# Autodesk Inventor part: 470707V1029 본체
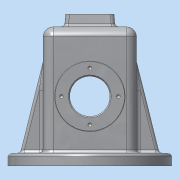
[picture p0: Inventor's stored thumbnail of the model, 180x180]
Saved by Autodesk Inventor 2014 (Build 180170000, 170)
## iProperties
Created: 2017-07
Part Number: 470707V1029 본체
Material: 알루미늄 6061
Document SubType Name: Modeling
Designer: 406-9
Density: 2.71 g/cm^3
Appearance: 알루미늄 - 평지
Author: 406-9
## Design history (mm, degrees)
sketch "스케치1"
  geometry: L1 (37, -37)-(-37, -37); L2 (-37, -37)-(-37, 37); L3 (-37, 37)-(37, 37); L4 (37, 37)-(37, -37); L5 (37, -37)-(-37, 37); L6 (-37, -37)-(37, 37); 1 further point
  constraints: 12 end point, 2 midpoint, 2 parallel, 1 horizontal, 1 perpendicular
  dimensions: "d0" = 74 distance of L1.end L2.end; "d1" = 74 distance of L2.end L3.end
extrude "돌출1" new body sketch "스케치1" distance "d2" = 100; taper "d3" = 0 deg
feature "쉘1" dims "d4" = 5
sketch "스케치3"
  geometry: L1 (0, 0)-(65, 0); L2 (0, 0)-(0, 75); 1 further point; 1 other entity
  constraints: 4 end point, 2 horizontal, 1 coincident, 1 perpendicular, 4 other
  dimensions: "d8" = 65 distance of L1.start L1.end; "d9" = 75 distance of L1.start L2.end
extrude "돌출3" join sketch "스케치3" distance "d10" = 10; taper "d11" = 0 deg
sketch "스케치4"
  geometry: L1 (-32, 32)-(32, 32) reference; L2 (-32, -32)-(-32, 32) reference; L3 (32, 32)-(32, -32) reference; L4 (32, -32)-(-32, -32) reference; 1 further point
extrude "돌출4" cut sketch "스케치4" distance "d12" = 10; taper "d13" = 0 deg
sketch "스케치5"
  geometry: L1 (-28, -110)-(102, -110) reference; L2 (37, -110)-(37, -55); C1 r 27.5 at (37, -55); 1 further point
  constraints: 2 end point, 1 centre point, 1 coincident, 1 midpoint, 1 perpendicular
  dimensions: "d14" = 55 distance of L2.start L2.end; "d15" = 55 diameter of C1
extrude "돌출5" join sketch "스케치5" distance "d16" = 13; taper "d17" = 0 deg
node "작업 평면1"
sketch "스케치6"
  geometry: L1 (-32, -10)-(-32, 95) reference; L2 (32, -10)-(32, 95) reference; L3 (-32, 72.5)-(-25, 65.5); L4 (-25, 65.5)-(-25, 45); L5 (-50, 72.5)-(-50, 17.5) reference; L6 (50, 72.5)-(50, 17.5) reference; L7 (-32, 72.5)-(-32, 45); L8 (-32, 45)-(-25, 45); L9 (32, 45)-(50, 45); 1 further point
  constraints: 10 end point, 2 point on line, 1 collinear, 1 midpoint, 1 parallel
  dimensions: "d19" = 135 deg angle of L1 L3; "d21" = 7 distance between parallel lines of L4 L1
revolve "회전1" sketch "스케치6" stored, may be unused: angle "d22" = 90 deg
sketch "스케치7"
  geometry: L1 (-65, -55)-(65, -55) reference; L2 (0, -55)-(0, 0); 2 further points
  constraints: 2 end point, 1 coincident, 1 midpoint, 1 perpendicular
  dimensions: "d23" = 55 distance of L2.start L2.end
hole "구멍1" sketch "스케치7" at (0, 0) diameter "d24" = 32; stored, may be unused: countersink angle "d28" = 90 deg, drill point angle "d30" = 118 deg; dims "d25" = 6, "d26" = 4, "d27" = 2, "d29" = 8
sketch "스케치8" dims "d32" = 45
  geometry: L1 (-65, -55)-(65, -55) reference; L2 (0, -55)-(0, 0); L3 (0, 0)-(0, 34); 3 further points
  constraints: 4 end point, 1 coincident, 1 collinear, 1 midpoint, 1 perpendicular, 1 point on line, 1 vertical alignment, 2 other
  dimensions: "d31" = 55 distance of L2.start L2.end
hole "구멍2" sketch "스케치8" at (0, 22.5) diameter "d33" = 3.242; stored, may be unused: countersink angle "d37" = 90 deg, drill point angle "d39" = 118 deg; dims "d34" = 8, "d35" = 4, "d36" = 2, "d38" = 10
sketch "스케치9"
  geometry: L1 (0, 0)-(0, 58); 1 further point
  constraints: 2 end point, 1 coincident, 1 vertical
  dimensions: "d43" = 58 distance of L1.start L1.end
hole "구멍3" sketch "스케치9" at (0, 58) diameter "d44" = 10; stored, may be unused: countersink angle "d48" = 90 deg, drill point angle "d50" = 0 deg; dims "d45" = 8, "d46" = 4, "d47" = 2, "d49" = 10
sketch "스케치11"
  geometry: L1 (20, -20)-(-20, -20); L2 (-20, -20)-(-20, 20); L3 (-20, 20)-(20, 20); L4 (20, 20)-(20, -20); L5 (20, -20)-(-20, 20); L6 (-20, -20)-(20, 20); 1 further point
  constraints: 12 end point, 2 midpoint, 2 parallel, 1 horizontal, 1 perpendicular
  dimensions: "d56" = 40 distance of L1.end L2.end; "d57" = 40 distance of L2.end L3.end
extrude "돌출6" join sketch "스케치11" distance "d58" = 10; taper "d59" = 0 deg
sketch "스케치12"
  geometry: 2 further points
  constraints: 1 coincident
hole "구멍4" sketch "스케치12" at (0, 0) diameter "d60" = 21; stored, may be unused: countersink angle "d64" = 90 deg, drill point angle "d66" = 0 deg; dims "d61" = 8, "d62" = 28, "d63" = 4, "d65" = 10
sketch "스케치13"
  geometry: L1 (35.52, 78.131)-(56.247, -5); L2 (-65, 0)-(65, 0) reference; L3 (-65, 0)-(-37, 0) reference; L4 (-37, 0)-(-37, 100) reference; L5 (-37, 100)-(-20, 100) reference; L6 (-20, 100)-(-20, 110) reference; L7 (-20, 110)-(-14, 110) reference; L8 (-14, 110)-(-14, 106) reference; L9 (-14, 106)-(-10.5, 106) reference; L10 (-10.5, 106)-(-10.5, 95) reference; L11 (-10.5, 95)-(-32, 95) reference; L12 (-32, 95)-(-32, -10) reference; L13 (-32, -10)-(-65, -10) reference; L14 (-65, -10)-(-65, 0) reference; L15 (37, 0)-(65, 0) reference; L16 (65, 0)-(65, -10) reference; L17 (65, -10)-(32, -10) reference; L18 (32, -10)-(32, 95) reference; L19 (32, 95)-(10.5, 95) reference; L20 (10.5, 95)-(10.5, 106) reference; L21 (10.5, 106)-(14, 106) reference; L22 (14, 106)-(14, 110) reference; L23 (14, 110)-(20, 110) reference; L24 (20, 110)-(20, 100) reference; L25 (20, 100)-(37, 100) reference; L26 (37, 100)-(37, 0) reference; L27 (35.52, 78.131)-(35.52, -5); L28 (35.52, -5)-(56.247, -5); L29 (55, 0)-(55, 12); 1 further point
  constraints: 8 end point, 3 perpendicular, 2 point on line
  dimensions: "d68" = 14 deg angle of L16 L1
extrude "돌출7" join sketch "스케치13" stored distance "d69" = 10; taper "d70" = 0 deg
node "작업 평면2"
fillet "모깎기1" dims "d72" = 2.5
fillet "모깎기2" dims "d73" = 8
fillet "모깎기3" dims "d74" = 3
chamfer "모따기1" distance "d75" = 1; stored, may be unused: second distance "d76" = 2, angle "d77" = 45 deg
fillet "모깎기5" dims "d79" = 3
feature "면 기울기1" dims angle "d80" = 5 deg
fillet "모깎기7" dims "d82" = 3
fillet "모깎기8" dims "d83" = 0.5
fillet "모깎기9" dims "d84" = 8
fillet "모깎기10" dims "d85" = 3
fillet "모깎기11" dims "d86" = 3
fillet "모깎기12" dims "d87" = 0.5
fillet "모깎기13" dims "d88" = 3
sketch "스케치15"
  geometry: L1 (45.137, -18)-(12.863, -18) reference; L2 (-8, 89)-(-8, 0) reference; 2 further points
  constraints: 1 other
  dimensions: "d93" = 30 distance from line of point (29, 12) L1; "d94" = 37 distance from line of L2 point (29, 12)
feature "엠보싱2" sketch "스케치15" dims "d95" = 0.5, "d96" = 0
node "솔리드1"
mirror "대칭1"
mirror "대칭2"
pattern_circular "원형 패턴1" dims angle "d41" = 360 deg
mirror "대칭3"
mirror "대칭4"
mirror "대칭5"
node "절단 모서리 투영2"
other parameters: "d71" = 0
